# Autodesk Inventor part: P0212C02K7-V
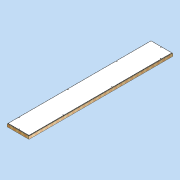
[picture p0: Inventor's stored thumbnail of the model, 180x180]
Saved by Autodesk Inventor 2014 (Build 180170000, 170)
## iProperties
Created: 2011-04
Part Number: P0212C02K7-V
Document SubType Name: Modeling
Designer: david.appleford
Density: 0.224578 g/cm^3
Description: 1w x 3w 02 Ceiling Panel - Locks 8
Mass: 36000 g
Surface Area: 45683.3 cm^2
Volume: 160301 cm^3
Cost Center: £132.00
Material: Generic
Appearance: Wood (Pine)
Justset: False
Author: david.appleford
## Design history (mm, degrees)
sketch "Sketch1"
  geometry: L1 (0, 0)-(610, 0); L2 (610, 0)-(610, 3660); L3 (610, 3660)-(0, 3660); L4 (0, 3660)-(0, 0); L5 (34, 3626)-(576, 3626); L6 (576, 3626)-(576, 34); L7 (576, 34)-(34, 34); L8 (34, 34)-(34, 3626)
  constraints: 16 end point, 4 parallel, 2 perpendicular, 1 horizontal, 3 other
  dimensions: "d0" = 610 distance between parallel lines of L2 L4 (= 0.5 x w); "d1" = 3660 distance between parallel lines of L1 L3 (= 3 x w); "d2" = 34 distance between parallel lines of L5 L3 (= 0.5 x t)
extrude "Extrusion1" new body sketch "Sketch1" distance "d3" = 68 (= t); taper "d4" = 0 deg
sketch "Sketch2"
  geometry: L1 (576, 3626)-(576, 34) reference; L2 (34, 3626)-(576, 3626) reference; L3 (34, 34)-(34, 3626) reference; L4 (576, 34)-(34, 34) reference; L5 (566, 3616)-(566, 44); L6 (566, 44)-(44, 44); L7 (44, 44)-(44, 3616); L8 (44, 3616)-(566, 3616); 1 further point
  constraints: 8 end point, 3 other
  dimensions: "d5" = 10 distance between parallel lines of L8 L2
extrude "Extrusion2" join sketch "Sketch2" distance "d6" = 9; taper "d7" = 0 deg
sketch "Sketch3"
  geometry: L1 (-44, 3616)-(-566, 3616) reference; L2 (-566, 3616)-(-566, 44) reference; L3 (-44, 44)-(-44, 3616) reference; L4 (-566, 44)-(-44, 44) reference; 1 further point
extrude "Extrusion3" join sketch "Sketch3" distance "d8" = 6 (= sw); taper "d9" = 0 deg
sketch "Sketch4"
  geometry: L1 (34, 3626)-(576, 3626) reference; L2 (576, 3626)-(576, 34) reference; L3 (576, 34)-(34, 34) reference; L4 (34, 34)-(34, 3626) reference; 9 further points
  constraints: 4 vertical alignment
  dimensions: "d10" = 28 distance from line of point (305, 3598) L1 (= k); "d11" = 28 distance from line of L2 point (548, 3355) (= k); "d13" = 28 distance from line of point (62, 305) L4 (= k); "d14" = 305 horizontal distance of point (305, 3598) point (0, 0) (= 0.25 x w); "d16" = 305 vertical distance of point (62, 305) point (0, 0) (= 0.25 x w); "d17" = 1220 distance of point (62, 305) point (62, 1525) (= w); "d18" = 1220 distance of point (62, 2745) point (62, 1525) (= w); "d19" = 610 vertical distance of point (548, 915) point (62, 305) (= 0.5 x w); "d20" = 1220 distance of point (548, 915) point (548, 2135) (= w); "d21" = 1220 distance of point (548, 3355) point (548, 2135) (= w); "d29" = 28 distance from line of point (305, 62) L3 (= k); "d30" = 305 horizontal distance of point (0, 0) point (305, 62) (= 0.25 x w)
hole "Hole1" sketch "Sketch4" at (305, 3598), (62, 2745), (62, 1525), (62, 305), (548, 3355), (548, 2135), (548, 915), (305, 62) diameter "d22" = 16.3; stored, may be unused: countersink angle "d26" = 90 deg, drill point angle "d28" = 118 deg; dims "d23" = 6, "d24" = 4, "d25" = 2, "d27" = 9
chamfer "Chamfer1" distance "d31" = 3; stored, may be unused: second distance "d32" = 2, angle "d33" = 45 deg
body "Solid1"
node "Projected Loop1"
other parameters: "w" = 1220 [user parameter; used in 10 equation terms], "t" = 68 [user parameter; used in 2 equation terms], "e" = 16 [user parameter], "sw" = 6 [user parameter; used in 1 equation term], "sc" = 9 [user parameter], "sf" = 12 [user parameter], "k" = 28 [user parameter; used in 4 equation terms], "hd" = 12 [user parameter]
